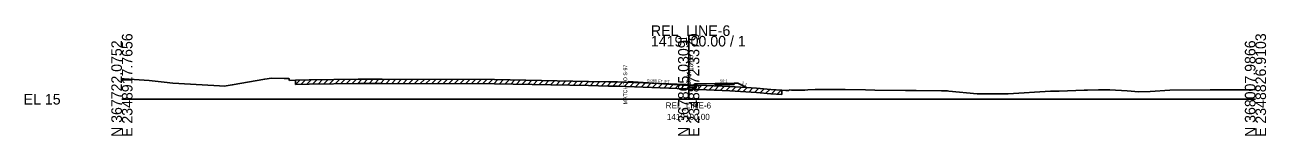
# Model space of a CAD drawing. Extents: x -26 to 403, y -10 to 6565.
# Drawn here: x -25.7 to 302.8, y 990.3 to 1019.6 of the extents above; entities that cross this region are included whole.
import ezdxf

# ---------------------------------------------------------------- set-up
doc = ezdxf.new("R2010")
doc.units = 0
for name, color, linetype in [('RD_GPK_XS_Cell', 7, 'Continuous'), ('RD_XS_CurbBase', 7, 'Continuous'), ('RD_XS_CurbFront', 7, 'Continuous'), ('RD_XS_CurbTop', 7, 'Continuous'), ('RD_XS_EarthShd', 7, 'Continuous'), ('RD_XS_ExGround', 7, 'Continuous'), ('RD_XS_ExPaveRet', 7, 'Continuous'), ('RD_XS_MatchLine', 7, 'Continuous'), ('RD_XS_Pave', 7, 'Continuous'), ('RD_XS_SW', 7, 'Continuous'), ('RD_XS_SWbase', 7, 'Continuous'), ('RD_XS_TieSlope', 7, 'Continuous'), ('RD_XS_TX_Elev_EX', 7, 'Continuous'), ('RD_XS_TX_Elev_PR', 7, 'Continuous'), ('RD_XS_TX_MatchLine', 7, 'Continuous'), ('RD_XS_TX_Slope', 7, 'Continuous'), ('RD_XS_TX_Station', 7, 'Continuous'), ('RD_XS_TX_TOC', 7, 'Continuous')]:
    doc.layers.add(name, color=color, linetype=linetype)

msp = doc.modelspace()

# ---------------------------------------------------------------- linework, layer by layer
at = {"layer": 'RD_GPK_XS_Cell'}
for p, q in [((150, 1000), (150, 1016.8)), ((0, 1000), (150, 1000)), ((150, 1000), (300, 1000))]:
    msp.add_line(p, q, dxfattribs=at)
at = {"layer": 'RD_XS_CurbBase'}
for p, q in [((151.5, 1003.05), (150, 1003.13)), ((152, 1003.05), (151.5, 1003.05)), ((152, 1004.05), (152, 1003.05))]:
    msp.add_line(p, q, dxfattribs=at)
at = {"layer": 'RD_XS_CurbFront'}
msp.add_line((150, 1003.13), (150, 1003.63), dxfattribs=at)
at = {"layer": 'RD_XS_CurbTop'}
for p, q in [((150, 1003.65), (150, 1003.63)), ((150, 1003.63), (151.42, 1003.55)), ((151.42, 1003.55), (151.5, 1004.05)), ((151.5, 1004.05), (152, 1004.05))]:
    msp.add_line(p, q, dxfattribs=at)
at = {"layer": 'RD_XS_EarthShd'}
for p, q in [((152, 1004.05), (157, 1004.15)), ((162, 1004.25), (163, 1004.27))]:
    msp.add_line(p, q, dxfattribs=at)
at = {"layer": 'RD_XS_ExGround'}
msp.add_lwpolyline([(0, 1005.44), (0.63, 1005.39), (7.25, 1005), (11.19, 1004.55), (13.46, 1004.31), (18.18, 1003.99), (25.82, 1003.55), (27.06, 1003.48), (29.22, 1003.82), (37.81, 1005.35), (39.58, 1005.6), (42.92, 1005.52), (43.72, 1005.5), (44.22, 1005.5), (44.38, 1005), (45.9, 1005.08), (49.53, 1005.14), (62.54, 1005.36), (68.88, 1005.3), (98.63, 1005.24), (123.53, 1004.75), (128.78, 1004.61), (131.2, 1004.6), (149.29, 1003.87), (150, 1003.84), (154.75, 1003.68), (160.86, 1003.4), (167.99, 1002.92), (171.77, 1002.6), (174.68, 1002.38), (175.74, 1002.32), (176.48, 1002.28), (176.69, 1002.48), (177.25, 1002.44), (178.32, 1002.4), (180.75, 1002.44), (181.52, 1002.47), (183.48, 1002.58), (191.41, 1002.55), (196.83, 1002.49), (199.29, 1002.42), (207.38, 1002.3), (210.19, 1002.33), (216.95, 1002.21), (218.54, 1002.19), (218.89, 1002.15), (226.32, 1001.43), (234.03, 1001.46), (234.52, 1001.47), (245.74, 1002.15), (246.88, 1002.18), (248.06, 1002.17), (254.71, 1002.4), (255.53, 1002.37), (258.42, 1002.5), (261.46, 1002.5), (266.09, 1002.21), (269.18, 1001.96), (272.13, 1002.02), (277.35, 1002.4), (288, 1002.49), (288.53, 1002.51), (290.81, 1002.5), (297.68, 1002.5), (300, 1002.56)], dxfattribs=at)
at = {"layer": 'RD_XS_ExPaveRet'}
for p, q in [((59.4, 1004.17), (60.56, 1005.33)), ((60.9, 1004.19), (62.06, 1005.36)), ((62.4, 1004.22), (63.53, 1005.35)), ((63.9, 1004.21), (65.03, 1005.34)), ((65.4, 1004.19), (66.53, 1005.32)), ((45.9, 1003.94), (47.06, 1005.1)), ((45.9, 1003.94), (45.9, 1005.08)), ((45.9, 1003.94), (49.53, 1004)), ((47.4, 1003.96), (48.56, 1005.12)), ((48.9, 1003.99), (50.06, 1005.15)), ((49.53, 1004), (62.54, 1004.22)), ((50.4, 1004.01), (51.56, 1005.17)), ((51.9, 1004.04), (53.06, 1005.2)), ((53.4, 1004.06), (54.56, 1005.23)), ((54.9, 1004.09), (56.06, 1005.25)), ((56.4, 1004.11), (57.56, 1005.28)), ((57.9, 1004.14), (59.06, 1005.3)), ((62.54, 1004.22), (68.88, 1004.16)), ((66.9, 1004.18), (68.03, 1005.31)), ((68.4, 1004.16), (69.54, 1005.3)), ((68.88, 1004.16), (98.63, 1004.1)), ((69.9, 1004.15), (71.04, 1005.3)), ((71.4, 1004.15), (72.54, 1005.29)), ((72.9, 1004.15), (74.04, 1005.29)), ((74.4, 1004.15), (75.54, 1005.29)), ((75.9, 1004.14), (77.04, 1005.28)), ((77.4, 1004.14), (78.54, 1005.28)), ((78.9, 1004.14), (80.04, 1005.28)), ((80.4, 1004.14), (81.54, 1005.28)), ((81.9, 1004.13), (83.04, 1005.27)), ((83.4, 1004.13), (84.54, 1005.27)), ((84.9, 1004.13), (86.04, 1005.27)), ((86.4, 1004.12), (87.54, 1005.27)), ((87.9, 1004.12), (89.04, 1005.26)), ((89.4, 1004.12), (90.54, 1005.26)), ((90.9, 1004.12), (92.04, 1005.26)), ((92.4, 1004.11), (93.54, 1005.25)), ((93.9, 1004.11), (95.04, 1005.25)), ((95.4, 1004.11), (96.54, 1005.25)), ((96.9, 1004.1), (98.04, 1005.25)), ((98.4, 1004.1), (99.52, 1005.23)), ((98.63, 1004.1), (123.53, 1003.61)), ((99.9, 1004.08), (101.02, 1005.2)), ((101.4, 1004.05), (102.52, 1005.17)), ((102.9, 1004.02), (104.02, 1005.14)), ((104.4, 1003.99), (105.52, 1005.11)), ((105.9, 1003.96), (107.02, 1005.08)), ((107.4, 1003.93), (108.52, 1005.05)), ((108.9, 1003.9), (110.02, 1005.02)), ((110.4, 1003.87), (111.52, 1004.99)), ((111.9, 1003.84), (113.02, 1004.96)), ((113.4, 1003.81), (114.52, 1004.93)), ((114.9, 1003.78), (116.02, 1004.9)), ((116.4, 1003.75), (117.52, 1004.87)), ((117.9, 1003.72), (119.02, 1004.84)), ((119.4, 1003.69), (120.52, 1004.81)), ((120.9, 1003.66), (122.02, 1004.78)), ((122.4, 1003.63), (123.52, 1004.75)), ((123.53, 1003.61), (128.78, 1003.47)), ((123.9, 1003.6), (125.01, 1004.71)), ((125.4, 1003.56), (126.51, 1004.67)), ((126.9, 1003.52), (128.01, 1004.63)), ((128.4, 1003.48), (129.53, 1004.61)), ((128.78, 1003.47), (131.2, 1003.46)), ((129.9, 1003.46), (131.04, 1004.6)), ((131.2, 1003.46), (149.29, 1002.72)), ((131.4, 1003.45), (132.5, 1004.55)), ((132.9, 1003.39), (134, 1004.48)), ((134.4, 1003.33), (135.5, 1004.42)), ((135.9, 1003.27), (137, 1004.36)), ((137.4, 1003.2), (138.5, 1004.3)), ((138.9, 1003.14), (140, 1004.24)), ((140.4, 1003.08), (141.5, 1004.18)), ((141.9, 1003.02), (143, 1004.12)), ((143.4, 1002.96), (144.5, 1004.06)), ((144.9, 1002.9), (146, 1004)), ((146.4, 1002.84), (147.5, 1003.94)), ((147.9, 1002.78), (149, 1003.88)), ((149.29, 1002.72), (150, 1002.7)), ((149.4, 1002.72), (150.5, 1003.82)), ((150, 1002.7), (154.75, 1002.54)), ((150.9, 1002.67), (152, 1003.77)), ((152.4, 1002.62), (153.5, 1003.72)), ((153.9, 1002.57), (155, 1003.67)), ((154.75, 1002.54), (160.86, 1002.25)), ((155.4, 1002.51), (156.49, 1003.6)), ((156.9, 1002.44), (157.99, 1003.53)), ((158.4, 1002.37), (159.49, 1003.46)), ((159.9, 1002.3), (160.99, 1003.39)), ((160.86, 1002.25), (167.99, 1001.78)), ((161.4, 1002.22), (162.47, 1003.29)), ((162.9, 1002.12), (163.97, 1003.19)), ((164.4, 1002.02), (165.47, 1003.09)), ((165.9, 1001.92), (166.97, 1002.99)), ((167.4, 1001.82), (168.46, 1002.88)), ((168.9, 1001.7), (169.95, 1002.76)), ((170.4, 1001.58), (171.45, 1002.63)), ((171.9, 1001.45), (172.96, 1002.51)), ((173.4, 1001.34), (174.46, 1002.4)), ((174.68, 1002.38), (174.68, 1001.24)), ((167.99, 1001.78), (171.77, 1001.46)), ((171.77, 1001.46), (174.68, 1001.24))]:
    msp.add_line(p, q, dxfattribs=at)
at = {"layer": 'RD_XS_MatchLine'}
msp.add_line((134, 1004.74), (134, 1004.48), dxfattribs=at)
at = {"layer": 'RD_XS_Pave'}
msp.add_line((134, 1004.74), (150, 1003.65), dxfattribs=at)
at = {"layer": 'RD_XS_SW'}
msp.add_line((157, 1004.15), (162, 1004.25), dxfattribs=at)
at = {"layer": 'RD_XS_SWbase'}
for p, q in [((157, 1003.81), (157, 1004.15)), ((162, 1003.91), (157, 1003.81)), ((162, 1004.25), (162, 1003.91))]:
    msp.add_line(p, q, dxfattribs=at)
at = {"layer": 'RD_XS_TieSlope'}
msp.add_line((163, 1004.27), (165.34, 1003.1), dxfattribs=at)

# ---------------------------------------------------------------- texts
at = {"layer": 'RD_GPK_XS_Cell'}
for s, p in [('REL_LINE-6', (140, 1016.8)), ('1419+00.00 / 1', (140, 1014)), ('EL 15', (-26, 998.6))]:
    msp.add_text(s, height=2.8, dxfattribs=at).set_placement(p)
for s, p in [('N 367722.0752', (0, 990)), ('E 2348917.7656', (2.8, 990)), ('N 367865.0309', (150, 990)), ('E 2348872.3379', (152.8, 990)), ('N 368007.9866', (300, 990)), ('E 2348826.9103', (302.8, 990))]:
    msp.add_text(s, height=2.8, rotation=90, dxfattribs=at).set_placement(p)
at = {"layer": 'RD_XS_TX_Elev_EX'}
msp.add_text('18.84', height=1, rotation=90, dxfattribs=at).set_placement((150.5, 1003.84))
at = {"layer": 'RD_XS_TX_Elev_PR'}
msp.add_text(' 18.65', height=1.2, rotation=90, dxfattribs=at).set_placement((151.2, 1007.11))
at = {"layer": 'RD_XS_TX_MatchLine'}
msp.add_text('MATCH TO S-97', height=1, rotation=90, dxfattribs=at).set_placement((133.73, 998.66))
at = {"layer": 'RD_XS_TX_Slope'}
for s, rotation, p in [('0.068 FT./FT.', 356.1044, (139, 1004.65)), ('50:1', 1.1458, (158.29, 1004.47)), ('2:1', 333.4349, (163.94, 1004.08))]:
    msp.add_text(s, height=0.75, rotation=rotation, dxfattribs=at).set_placement(p)
at = {"layer": 'RD_XS_TX_Station'}
for s, p in [('REL_LINE-6', (143.92, 997.55)), ('1419+00.00', (144.23, 994.53))]:
    msp.add_text(s, height=1.6, dxfattribs=at).set_placement(p)
at = {"layer": 'RD_XS_TX_TOC'}
msp.add_text('TOCRT', height=0.05, dxfattribs=at).set_placement((151.22, 1004))

doc.saveas('drawing.dxf')
